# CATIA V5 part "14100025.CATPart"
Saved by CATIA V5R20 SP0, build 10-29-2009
Part number: 14100025
Definition: NONE
Nomenclature: 14100025
Source: Unknown
Description: 14100025
Bounding box of the stored display mesh (mm): x -12.5 to 50, y -64 to 53.915, z -54.1 to 54.1
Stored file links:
  C:\Users\Utente\Desktop\IO LAVORO\3D X SITO CF\X SITO\PLASTICA\RF2\14100025.CATPart
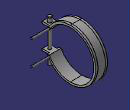
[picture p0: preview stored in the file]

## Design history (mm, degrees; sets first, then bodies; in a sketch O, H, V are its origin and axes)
Body1 "14100025" (main body)
  Solid1: solid without history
